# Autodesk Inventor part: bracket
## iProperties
Author: Administrator
Created: 2001-01
Part Number: bracket
Document SubType Name: Modeling
Designer: Administrator
Control State: 0
Master: False
Checked Out: False
PropertySet Name: Design Tracking Control
Shininess: 0.0
PropertySet Name: _Private Model Information
Density: 0.0
Volumn: 0.0
Area: 0.0
PropertySet Name: Model Information
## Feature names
1. Extrusion1
2. Extrusion2
3. Hole1
4. Extrusion3
5. Extrusion4
